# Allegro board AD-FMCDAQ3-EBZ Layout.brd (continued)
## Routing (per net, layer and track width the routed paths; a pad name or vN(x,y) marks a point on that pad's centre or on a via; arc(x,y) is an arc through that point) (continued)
FMC_SERDOUT0_N: length 40
  TOP w0.254: P501.A11 v4(68.13,22.21)
  BOTTOM w0.254: v4(68.13,22.21) 67.98,22.06 67.18,22.06 65.84,20.72 65.84,19.45 64.01,17.61 46.94,17.61 42.5,22.06 37.04,22.06 36.72,22.37 33.1,22.37 C20.1
FMC_SERDOUT0_P: length 40
  TOP w0.254: P501.A10 v4(68.13,21.4)
  BOTTOM w0.254: v4(68.13,21.4) 67.98,21.55 67.39,21.55 66.35,20.51 66.35,19.24 64.22,17.1 46.73,17.1 42.29,21.55 36.83,21.55 36.51,21.87 33.1,21.87 C8.1
FMC_SERDOUT1_N: length 35.5
  TOP w0.254: P501.C7 v4(65.59,17.1)
  BOTTOM w0.254: C85.1 33.1,20.98 35.96,20.98 36.53,20.41 41.74,20.41 46.31,15.83 63.88,15.83 64.87,16.82 65.31,16.82 v4(65.59,17.1)
FMC_SERDOUT1_P: length 35.4
  TOP w0.254: P501.C6 v4(65.59,16.32)
  BOTTOM w0.254: v4(65.59,16.32) 65.08,16.32 64.09,15.33 46.1,15.33 41.53,19.9 36.32,19.9 35.75,20.47 33.1,20.47 C84.1
FMC_SERDOUT2_N: length 40.9
  TOP w0.254: P501.A7 v4(68.13,17.13)
  BOTTOM w0.254: v4(68.13,17.13) 67.96,16.96 67.4,16.96 66.63,16.2 66.63,15.51 63.24,12.12 61.79,12.12 59.6,14.31 45.55,14.31 41.1,18.75 36.02,18.75 35.2,19.58 33.1,19.58 C87.1
FMC_SERDOUT2_P: length 40.9
  TOP w0.254: P501.A6 v4(68.13,16.32)
  BOTTOM w0.254: C86.1 33.1,19.07 34.99,19.07 35.81,18.25 40.89,18.25 45.34,13.8 59.39,13.8 61.57,11.62 63.45,11.62 67.14,15.3 67.14,15.99 67.61,16.46 67.99,16.46 68.08,16.37 v4(68.13,16.32)
FMC_SERDOUT3_N: length 39.4
  TOP w0.254: P501.A3 v4(68.28,12.02)
  BOTTOM w0.254: v4(68.28,12.02) 68.08,11.82 67.59,11.82 66.19,10.42 61.33,10.42 59.22,12.53 45.17,12.53 40.59,17.1 35.7,17.1 34.63,18.18 33.1,18.18 C92.1
FMC_SERDOUT3_P: length 39.4
  TOP w0.254: P501.A2 v4(68.28,11.31)
  BOTTOM w0.254: v4(68.28,11.31) 67.8,11.31 66.4,9.92 61.12,9.92 59.01,12.02 44.96,12.02 40.38,16.6 35.49,16.6 34.41,17.67 33.1,17.67 C88.1
FMC_SPI_SCLK: length 22.8
  TOP w0.152: v1(69.42,24.6) 69.42,29.04 69.55,29.17 69.55,34.5 71.07,36.03 72.73,36.03 72.98,36.28 R91.1
  L2_AGND w0.152: v1(64.3,23.7) 63.66,24.34 v2(63.66,24.65) ; v1(69.42,24.6) v2(69.42,23.96)
  L8_SIG w0.152: v2(69.42,23.96) 68.97,23.96 68.81,24.11 64.22,24.11 v2(63.66,24.65)
FMC_SPI_SDIO: length 23.4
  TOP w0.152: v1(69.93,26.12) 69.93,18.25 70.57,17.61 76.41,17.61 76.98,18.18 R115.1
  L2_AGND w0.152: v1(64.3,26.24) 64.3,26.21 v2(63.84,25.74) ; v1(69.93,26.12) v2(69.93,25.49)
  L8_SIG w0.152: v2(63.84,25.74) 64.34,25.74 64.6,25.49 v2(69.93,25.49)
FMC_SPI_SDIO_CTRL: length 12
  TOP w0.152: U9.5 v1(74.63,20.41)
  L2_AGND w0.152: v1(65.57,22.43) 65.62,22.43 v2(65.99,22.79) ; v1(74.63,20.41) v2(74.63,21.17)
  L8_SIG w0.152: v2(65.99,22.79) 66.65,23.45 68.46,23.45 70.36,21.55 74.25,21.55 v2(74.63,21.17)
FMC_SYSREF_N: length 39.2
  TOP w0.254: 30.56,41.87 v1(30.62,41.87) ; P501.D18 v1(64.03,30.97)
  L2_AGND w0.254: v1(30.62,41.87) v2(31.07,41.64) ; v1(64.03,30.97) v2(63.56,30.97)
  L8_SIG w0.254: v2(31.07,41.64) 32.4,41.64 33.18,40.85 41.74,40.85 42.37,41.49 45.17,41.49 48.98,37.68 55.9,37.68 62.91,30.67 63.25,30.67 v2(63.56,30.97)
FMC_SYSREF_N_A: length 3.7
  TOP w0.254: R112.2 29.86,41.8 R114.2 28.37,41.8 27.82,41.25 27.82,39.97 U7.71
FMC_SYSREF_P: length 39.2
  TOP w0.254: P501.D17 v1(64.05,30.16) ; R113.1 v1(31.51,40.98)
  L2_AGND w0.254: v1(64.05,30.16) v2(63.56,30.16) ; v1(31.51,40.98) v2(31.07,40.85)
  L8_SIG w0.254: v2(63.56,30.16) 62.7,30.16 55.69,37.17 48.77,37.17 44.96,40.98 42.58,40.98 41.95,40.34 32.97,40.34 32.19,41.13 31.35,41.13 v2(31.07,40.85)
FMC_SYSREF_P_A: length 3.7
  TOP w0.254: U7.70 28.33,41.04 28.58,41.3 28.97,41.3 R114.1 29.23,41.3 30.43,41.3 R113.2
FMC_VADJ: length 101.2
  TOP w0.254: U9.1 73.19,18.96 v1(72.73,18.5) ; C235.1 71.07,27.77 71.59,28.28 U13.1 ; R119.2 72.41,39.07 72.09,39.07 71.71,39.46 71.46,39.46 C236.1 71.07,42.12 71.59,42.63 U12.1
  TOP w0.305: P501.H40 P501.G39 v1(61.76,59.26) 61.76,60.12 64.72,63.08 R8.1 64.72,66.32 v4(64.03,67.01)
  L2_AGND w0.254: v1(72.73,18.5) v2(72.09,18.5) ; v1(71.07,39.71) v2(71.07,40.34) ; v1(71.07,25.36) v2(71.07,25.99) ; v1(43.9,56.85) v2(44.4,56.85)
  L2_AGND w0.305: v1(61.76,59.26) v2(62.41,58.61) v1(63.03,57.99)
  L3_SIG w0.305: v2(71.33,55.84) 71.96,55.2 71.96,52.16 70.44,50.63 70.44,45.04 71.07,44.41 v2(71.07,40.34) 70.69,39.96 70.69,31.2 71.07,30.82 v2(71.07,25.99) 71.07,19.52 v2(72.09,18.5)
  L8_SIG w0.305: v2(44.4,56.85) 43.64,57.62 43.64,60.54 44.4,61.3 51.77,61.3 54.46,58.61 v2(62.41,58.61) 63.79,57.24 69.93,57.24 v2(71.33,55.84)
LDO_VCO_2P5: length 4.2
  TOP w0.305: C103.1 23.07,31.58 C62.1 24.47,31.58 25.14,32.26 U7.15
LF_EXT_CAP: length 4.7
  TOP w0.152: U7.7 26.63,36.26 26.08,36.26 25.93,36.41 25.93,36.98 25.57,37.33 C2.1 R2.1
LF_PLL2: length 1.2
  TOP w0.152: R83.2 25.45,32.76 U7.14
OUT0_N: length 14.1
  BOTTOM w0.203: U1.52 27.47,49.09 27.45,49.11 26.43,49.11 26.27,49.26
  BOTTOM w0.254: 26.27,49.26 24.59,50.94 24.59,55.25 24,55.84 23.7,55.84 R22.1 22.43,55.84 21.93,55.84 20.91,54.82 T2.1
OUT0_P: length 14.1
  BOTTOM w0.203: U1.53 27.47,49.59 27.45,49.57 26.69,49.57 26.63,49.62
  BOTTOM w0.254: T2.3 20.91,57.36 21.93,56.35 22.43,56.35 R15.2 23.7,56.35 24.21,56.35 25.1,55.46 25.1,51.16 26.63,49.62
OUT1_N: length 14.9
  BOTTOM w0.203: U1.45 28.22,45.54 26.31,45.54 26.09,45.32
  BOTTOM w0.254: 26.09,45.32 24.27,43.51 24.27,38.33 24,38.06 23.7,38.06 R23.2 22.43,38.06 21.93,38.06 20.91,39.07 T1.3
OUT1_P: length 14.9
  BOTTOM w0.203: U1.44 26.57,45.09 26.44,44.96
  BOTTOM w0.254: 26.44,44.96 24.78,43.3 24.78,38.12 24.21,37.55 23.7,37.55 R25.1 22.43,37.55 21.93,37.55 20.91,36.53 T1.1
PWRGD: length 230
  TOP w0.152: v4(39.71,19.26) 38.94,18.5 37.8,18.5 37.51,18.21 U17.5 ; U19.5 17.39,59.44 v4(17.23,59.27)
  TOP w0.254: R32.2 v1(51.64,53.55) ; 9.35,51.65 v4(8.21,51.65)
  TOP w0.305: U4.1 51.18,50.63 50.84,50.63 50.54,50.94 50.54,53.34 R32.2 ; v4(9.73,5.17) 10.03,5.46 U5.5
  L2_AGND w0.152: v1(51.64,53.55) v2(52.15,53.55)
  L3_SIG w0.152: v4(69.05,31.96) 70.19,33.09 70.19,39 69.93,39.25 69.93,51.65 v4(71.33,53.04) ; v4(17.23,59.27) 17.23,59.01 15.96,57.74 12.27,57.74 11.38,56.85 11.38,54.82 v4(8.21,51.65) 7.32,50.76 7.32,43.77 8.26,42.83 8.26,42.82 11.38,39.7 11.38,11.13 9.23,8.98 9.23,5.67 v4(9.73,5.17) ; v4(51.39,7.45) 48.85,9.99 47.2,9.99 39.71,17.48 v4(39.71,19.26)
  L8_SIG w0.152: v4(8.21,51.65) 9.48,52.92 23.83,52.92 24.85,53.93 29.55,53.93 30.43,54.82 30.43,55.2 31.32,56.09 42.88,56.09 44.28,54.7 51.01,54.7 v2(52.15,53.55) 53.55,53.55 56.22,50.89 65.87,50.89 66.76,51.77 70.06,51.77 v4(71.33,53.04)
  L8_SIG w0.305: v4(51.39,7.45) 49.99,6.05 28.91,6.05 28.02,5.17 v4(9.73,5.17)
  BOTTOM w0.254: v4(69.05,31.96) 68.92,31.83 U3.21 ; v4(71.33,53.04) 71.2,52.92 U6.21
  BOTTOM w0.305: U11.7 v4(51.39,7.45)
SPI_SCLK: length 123.9
  TOP w0.152: R101.1 v1(28.66,28.09)
  L2_AGND w0.152: v2(28.66,28.72) v1(28.66,28.09) ; v2(73.23,48.09) v1(73.23,48.73)
  L3_SIG w0.152: v2(31.7,13.04) 31.32,13.04 30.82,13.55 30.82,13.8 30.05,14.56 30.05,23.2 32.21,25.36 32.21,26.63 31.83,27.01 30.37,27.01 v2(28.66,28.72) 28.66,29.17 28.91,29.42 28.91,30.82 27.89,31.84 27.89,34.76 25.93,36.72 25.93,40.15 v2(26.31,40.53) ; v2(73.23,48.09) 74.25,47.08 74.25,43.27 77.17,40.34 77.17,36.87 76.15,35.86 76.15,21.63 73.11,18.58 73.11,12.91 v2(72.09,11.9)
  L8_SIG w0.152: v2(31.7,13.04) 33.36,13.04 33.99,13.67 44.91,13.67 46.18,12.4 54.06,12.4 56.09,10.37 69.8,10.37 71.33,11.9 v2(72.09,11.9)
  L9_AGND w0.152: v2(31.7,13.04) 29.55,13.04 v3(28.4,11.9) ; v2(28.66,28.72) v3(28.59,28.66) ; v3(26.31,41.04) v2(26.31,40.53)
  BOTTOM w0.152: v3(26.31,41.04) 26.46,41.2 27.37,41.2 28.03,40.53 R106.2
SPI_SDIO: length 97.1
  TOP w0.152: R118.2 77.42,19.45 77.42,17.74 76.66,16.98 v1(76.66,11.64) ; R4.1 v1(29.55,28.09)
  L2_AGND w0.152: v1(76.66,11.64) v2(76.66,10.88) ; v2(29.8,28.67) 29.8,28.66 29.55,28.41 v1(29.55,28.09)
  L3_SIG w0.152: v2(31.7,11.9) 32.21,12.4 32.21,13.29 31.96,13.55 31.45,13.55 31.2,13.8 31.2,13.93 30.43,14.69 30.43,23.07 32.59,25.23 32.59,26.76 31.96,27.39 30.82,27.39 29.8,28.41 v2(29.8,28.67) 29.79,28.67 29.55,28.91 29.55,30.69 28.28,31.96 28.28,34.88 26.62,36.53 26.62,38.95 27.01,39.33 v2(27.01,40.22)
  L8_SIG w0.152: v2(76.66,10.88) 70.95,10.88 70.06,9.99 55.83,9.99 53.8,12.02 45.93,12.02 44.66,13.29 34.24,13.29 32.85,11.9 v2(31.7,11.9)
  L9_AGND w0.152: v3(30.43,28.66) 29.81,28.66 v2(29.8,28.67) ; v2(31.7,11.9) v3(31.2,11.9) ; v2(27.01,40.22) v3(27.01,40.79)
  BOTTOM w0.152: R107.2 29.08,40.36 28.86,40.14 27.65,40.14 v3(27.01,40.79) ; R105.1 30.43,12.66 v3(31.2,11.9)
SW1: length 17.3
  BOTTOM w0.305: 66.52,51.53 66.4,51.42 U6.7 ; 66.52,51.53 U6.6 ; 66.52,51.53 66.76,51.77 67.02,51.77 ; 63.6,60.42 63.43,60.59 R3.1 ; 66.63,56.22 67.02,55.83 U6.14 67.02,52.8 U6.PAD2 67.02,52.54 67.02,51.77 ; 67.02,51.77 U6.5
  BOTTOM w0.508: 63.58,58.12 L1.1 ; L1.1 64.38,56 64.34,55.97 ; L1.1 65.18,58.12 ; L1.1 64.38,60.32 ; CBST1.2 66.82,59.71
  vias: v3(64.15,59.71) v3(64.15,59.27) v3(64.15,57.62) v3(64.15,57.11) v3(64.15,56.6) v3(64.6,59.71) v3(64.6,59.27) v3(64.6,57.62) v3(64.6,57.11) v3(64.6,56.6) v3(66.64,53.26) v3(66.64,52.75) v3(66.64,52.22) v3(66.65,51.57) v3(67.15,53.74) v3(67.15,53.26) v3(67.15,52.75) v3(67.15,52.22) v3(67.14,51.55)
UNNAMED_2_AD9152_I234_I120: length 4
  TOP w0.152: v4(26.5,50.78) 25.66,51.62 R17.2
  BOTTOM w0.152: v4(26.5,50.78) 27.18,50.78 27.38,50.59 U1.55
UNNAMED_2_AD9152_I234_LDOBYP1: length 2.4
  TOP w0.356: v4(28.15,52.1) 28.15,52.18 29.01,53.04 C199.2
  BOTTOM w0.152: v4(28.15,52.1) 28.47,51.79 U1.1
UNNAMED_2_AD9152_I234_LDOBYP2: length 4.3
  BOTTOM w0.152: C39.1 40.21,47.71 38.88,47.71 38.76,47.59 U1.22
UNNAMED_2_AD9152_I234_PAPOUT0: length 3.5
  BOTTOM w0.152: U1.37 31.46,43.25 31.02,42.81 31.02,41.86 R20.1
UNNAMED_2_AD9152_I234_REFCLK: length 5.4
  BOTTOM w0.152: 27.77,55.71 28.66,54.82 29.55,54.82 29.96,54.41 U1.3
UNNAMED_2_AD9152_I234_REFCLK_1: length 4.3
  BOTTOM w0.152: U1.4 30.46,54.79 29.55,55.71
UNNAMED_2_AD9152_I234_RESETB: length 6
  BOTTOM w0.152: R122.1 33.99,55.08 32.96,54.05 U1.9
UNNAMED_2_AD9152_I234_SPICLK: length 3.9
  BOTTOM w0.152: U1.40 29.96,42.05 29.48,41.56 28.7,41.56 R106.1
UNNAMED_2_AD9152_I234_SPISDIO: length 3.5
  BOTTOM w0.152: U1.39 30.46,42.15 29.48,41.17 R107.1
UNNAMED_2_CAP_I167_N2: length 3.6
  TOP w0.508: C44.2 13.54,39.33 v4(12.53,38.31)
  BOTTOM w0.508: T4.5 13.8,38.31 v4(12.53,38.31)
UNNAMED_2_CAP_I184_N2: length 2.9
  TOP w0.508: C42.2 v4(12.53,56.09)
  BOTTOM w0.508: T3.5 v4(12.53,56.09)
UNNAMED_2_CNBNC5P_I224_CNTR: length 6.6
  BOTTOM w0.381: T4.3 9.22,40.34 TX_B.1
UNNAMED_2_CNBNC5P_I229_CNTR: length 6.6
  BOTTOM w0.381: TX_A.1 9.22,53.55 T3.1
UNNAMED_2_XFMRETC1_I243_N3: length 3.3
  BOTTOM w0.254: T2.4 15.96,57.36 14.69,58.63 T3.4
UNNAMED_2_XFMRETC1_I243_N4: length 3.3
  BOTTOM w0.254: T2.5 15.96,54.82 14.69,53.55 T3.6
UNNAMED_2_XFMRETC1_I246_N3: length 3.3
  BOTTOM w0.254: T1.4 15.96,39.07 14.69,40.34 T4.4
UNNAMED_2_XFMRETC1_I246_N4: length 3.3
  BOTTOM w0.254: T4.6 14.69,35.26 15.96,36.53 T1.5
UNNAMED_4_AD9528_I220_OUT3: length 0.7
  TOP w0.254: U7.58 34.33,40.62 C189.1
UNNAMED_4_AD9528_I220_OUT3N: length 0.7
  TOP w0.254: C185.1 33.83,40.57 U7.59
UNNAMED_4_AD9528_I220_OUT10: length 5.4
  TOP w0.203: C194.1 37.55,27.39 37.51,27.42 37.28,27.42 37.22,27.48 35.67,27.48 34.85,28.3 34.85,29.66 34.83,29.68 U7.34
UNNAMED_4_AD9528_I220_OUT10N: length 5.2
  TOP w0.203: C193.1 37.79,28.03 37.65,27.88 37.47,27.88 37.07,28.28 36.87,28.28 36.53,27.94 35.86,27.94 35.31,28.49 35.31,28.79 35.51,29 35.51,29.17 35.31,29.38 35.31,29.65 35.33,29.68 U7.35
UNNAMED_4_AD9528_I220_SCLK: length 1.5
  TOP w0.152: U7.22 28.83,29.21 28.4,28.79 R101.2
UNNAMED_4_AD9528_I220_SDIO: length 1.4
  TOP w0.152: U7.23 29.29,30.02 R4.2
UNNAMED_4_CAP_I87_N1: length 9.1
  TOP w0.254: R58.1 15.58,36.46 Y1.5 16.08,35.19 16.08,34.5 16.72,33.87 20.15,33.87 C75.1
UNNAMED_4_CAP_I87_N2: length 5.5
  TOP w0.254: U7.12 25.31,33.76 25.08,33.99 23.96,33.99 R5.2 23.2,33.99 22.31,33.99 C75.2
UNNAMED_4_CAP_I90_N1: length 9
  TOP w0.254: C74.1 20.02,35.52 19.64,35.52 19.26,35.14 19.26,34.63 19,34.38 17.03,34.38 16.71,34.69 16.71,35.05 Y1.4 17.35,36.46 R48.1
UNNAMED_4_CAP_I90_N2: length 5.5
  TOP w0.254: C74.2 22.31,34.5 23.2,34.5 23.58,34.88 23.96,34.5 25.29,34.5 25.52,34.27 26.62,34.27 U7.11
UNNAMED_4_CAP_I173_N1: length 2
  TOP w0.152: R2.2 C61.1
UNNAMED_4_CAP_I217_N2: length 0.9
  TOP w0.305: R83.1 24.66,32.79 C62.2
UNNAMED_4_RES_I223_N2: length 4.6
  TOP w0.508: R6.2 R1.1 11.94,31.71 Y1.1
UNNAMED_5_AD9680_I130_SCLK: length 4
  BOTTOM w0.152: R104.2 28.66,12.85 28.66,14.58 27.86,15.37 27.76,15.37 27.6,15.54 U100.36
UNNAMED_5_AD9680_I130_SDIO: length 4
  BOTTOM w0.152: R105.2 29.04,13.23 29.04,14.6 28.1,15.53 U100.35
UNNAMED_5_CAP_I52_N2: length 0.9
  BOTTOM w0.254: R103.1 19.42,29.99 19.03,29.6 C108.2
UNNAMED_5_CAP_I53_N2: length 0.9
  BOTTOM w0.254: C187.2 19.38,29.23 19.75,29.6 R102.1
UNNAMED_5_CAP_I54_N2: length 1.6
  BOTTOM w0.254: R111.1 20.2,30.42 ; 20.2,30.42 20.73,30.95 C107.2 ; 20.2,30.42 R110.2
UNNAMED_5_CAP_I67_N2: length 1.5
  BOTTOM w0.254: 20.26,10.67 20.78,10.15 C190.2 ; 20.26,10.67 R129.1 ; 20.26,10.67 R128.2
UNNAMED_5_CAP_I68_N2: length 0.8
  BOTTOM w0.254: C188.2 18.94,11.47 R54.1
UNNAMED_5_CAP_I69_N2: length 0.8
  BOTTOM w0.254: 19.46,12.01 19.46,11.99 R53.1
UNNAMED_5_CAP_I181_N2: length 9.1
  BOTTOM w0.254: R108.1 23.83,28.32 23.83,28.93 C105.2 23.92,31.05 22.69,32.28 20.64,32.28 R110.1 19.49,31.09 R103.2
UNNAMED_5_CAP_I182_N1: length 8.6
  BOTTOM w0.254: R102.2 20.93,29.69 R111.2 21.16,29.93 21.42,29.93 21.8,30.31 21.8,30.82 21.33,31.29 21.33,31.47 21.63,31.77 22.48,31.77 23.41,30.84 23.41,29.32 23.23,29.14 C197.1 23.32,28.93 23.32,28.32 R109.1
UNNAMED_5_CAP_I183_N2: length 8.8
  BOTTOM w0.254: R53.2 R128.1 21.81,11.38 22.05,11.13 22.05,10.63 21.67,10.25 21.67,9.74 21.85,9.56 22.63,9.56 23.63,10.55 23.63,12.25 ; C115.2 23.63,12.25 ; 23.63,12.25 23.63,13.05 R126.1
UNNAMED_5_CAP_I184_N1: length 9.3
  BOTTOM w0.254: C116.1 24.14,12.25 ; 24.14,12.25 24.14,13.15 R127.1 ; 24.14,12.25 24.14,10.34 22.84,9.05 21.64,9.05 21.08,9.61 20.53,9.61 20.43,9.71 19.8,9.71 R129.2 R54.2
UNNAMED_5_CNBNC5P_I49_CNTR: length 5.8
  BOTTOM w0.381: RX_A.1 R121.1 T101.5
UNNAMED_5_CNBNC5P_I70_CNTR: length 5.8
  BOTTOM w0.381: T103.4 R138.1 RX_B.1
UNNAMED_6_CN400PAKV2_I20_TDI: length 1.3
  TOP w0.152: P501.D31 P501.D30
UNNAMED_7_AD7291_I66_DCAP: length 1.9
  TOP w0.152: C216.2 49.73,57.44 U18.8
UNNAMED_7_AD7291_I66_VIN5: length 4.6
  TOP w0.152: U18.3 45.79,61.04 R66.1 R67.2
UNNAMED_7_AD7291_I66_VIN6: length 7.3
  TOP w0.152: U18.4 46.69,60.54 45.93,59.78 45.93,58.12 45.67,57.87 45.42,57.87 45.17,57.62 R24.1 R26.2
UNNAMED_7_AD7291_I66_VIN7: length 10.1
  TOP w0.152: U18.5 46.83,60.04 46.31,59.52 46.31,58 46.06,57.74 46.06,54.19 R27.1 R36.2
UNNAMED_7_AD7291_I66_VREF: length 3.1
  TOP w0.152: C219.2 47.51,57.04 48.6,58.12 48.98,58.12 49.23,58.38 U18.7
UNNAMED_7_ADN4661_I56_DIN: length 9.2
  TOP w0.381: v4(40.98,27.01) 41.48,26.5 R9.1 U15.2
  BOTTOM w0.381: v4(40.98,27.01) 40.09,27.89 J1.1
UNNAMED_7_DIOLED_I43_P: length 1.8
  BOTTOM w0.152: R34.2 CR1.A
UNNAMED_7_ICFXL4245_I164_A0: length 3.4
  TOP w0.152: R74.2 72.98,25.61 72.75,25.84 U13.3
UNNAMED_7_ICFXL4245_I164_A1: length 1.5
  TOP w0.152: R41.2 73.49,25.74 73.25,25.97 U13.4
UNNAMED_7_ICFXL4245_I164_A2: length 3.5
  TOP w0.152: R75.2 74,25.74 73.74,25.99 73.74,26.73 U13.5
UNNAMED_7_ICFXL4245_I164_A3: length 1.5
  TOP w0.152: U13.6 74.25,25.99 74.5,25.74 R45.2
UNNAMED_7_ICFXL4245_I164_A4: length 3.5
  TOP w0.152: R71.2 75.01,25.74 74.76,25.99 74.76,26.73 U13.7
UNNAMED_7_ICFXL4245_I164_A5: length 1.6
  TOP w0.152: R65.2 75.52,25.74 75.25,26.01 U13.8
UNNAMED_7_ICFXL4245_I164_A6: length 3.5
  TOP w0.152: R73.2 76.03,25.74 75.75,26.01 U13.9
UNNAMED_7_ICFXL4245_I164_A7: length 1.6
  TOP w0.152: R70.2 76.54,25.87 76.25,26.15 U13.10
UNNAMED_7_ICFXL4245_I164_B0: length 3.4
  TOP w0.152: U13.21 73.25,33.66 R82.1
UNNAMED_7_ICFXL4245_I164_B1: length 1.4
  TOP w0.152: R76.1 73.75,31.76 U13.20
UNNAMED_7_ICFXL4245_I164_B2: length 3.4
  TOP w0.152: R84.1 74.25,33.67 U13.19
UNNAMED_7_ICFXL4245_I164_B3: length 1.4
  TOP w0.152: U13.18 74.75,31.77 R77.1
UNNAMED_7_ICFXL4245_I164_B4: length 3.4
  TOP w0.152: R78.1 75.25,33.66 U13.17
UNNAMED_7_ICFXL4245_I164_B5: length 1.5
  TOP w0.152: U13.16 75.75,31.75 R116.2
UNNAMED_7_ICFXL4245_I164_B6: length 3.4
  TOP w0.152: U13.15 76.25,33.65 R81.2
UNNAMED_7_ICFXL4245_I164_B7: length 2.5
  TOP w0.152: U13.14 76.79,29.29 R117.2
UNNAMED_7_ICFXL4245_I164_OEN: length 1.5
  TOP w0.152: U13.22 72.75,31.74 R80.2
UNNAMED_7_ICFXL4245_I164_TRN: length 2.6
  TOP w0.152: R79.1 72.47,25.74 72.21,26 U13.2
UNNAMED_7_ICFXL4245_I213_A0: length 3.4
  TOP w0.152: U12.3 72.75,40.19 72.98,39.96 R91.2
UNNAMED_7_ICFXL4245_I213_A1: length 1.5
  TOP w0.152: R85.1 73.49,40.09 73.25,40.32 U12.4
UNNAMED_7_ICFXL4245_I213_A2: length 3.4
  TOP w0.152: R92.1 74,40.09 73.75,40.33 U12.5
UNNAMED_7_ICFXL4245_I213_A3: length 1.5
  TOP w0.152: R86.2 74.5,40.09 74.25,40.34 U12.6
UNNAMED_7_ICFXL4245_I213_A4: length 3.5
  TOP w0.152: U12.7 74.75,40.35 75.01,40.09 R89.2
UNNAMED_7_ICFXL4245_I213_A5: length 1.6
  TOP w0.152: R87.2 75.52,40.09 75.25,40.36 U12.8
UNNAMED_7_ICFXL4245_I213_A6: length 3.5
  TOP w0.152: R90.2 76.03,40.09 75.75,40.36 U12.9
UNNAMED_7_ICFXL4245_I213_A7: length 1.6
  TOP w0.152: R88.2 76.54,40.22 76.25,40.5 U12.10
UNNAMED_7_ICFXL4245_I213_B0: length 3.4
  TOP w0.152: R99.1 73.25,48.01 U12.21
UNNAMED_7_ICFXL4245_I213_B1: length 1.4
  TOP w0.152: U12.20 73.75,46.11 R100.2
UNNAMED_7_ICFXL4245_I213_B2: length 3.4
  TOP w0.152: U12.19 74.25,48.02 R93.2
UNNAMED_7_ICFXL4245_I213_B3: length 1.4
  TOP w0.152: U12.18 74.75,46.12 R94.1
UNNAMED_7_ICFXL4245_I213_B4: length 3.4
  TOP w0.152: U12.17 75.25,48.02 R97.1
UNNAMED_7_ICFXL4245_I213_B5: length 1.5
  TOP w0.152: R95.1 75.75,46.1 U12.16
UNNAMED_7_ICFXL4245_I213_B6: length 3.4
  TOP w0.152: U12.15 76.25,48 R98.1
UNNAMED_7_ICFXL4245_I213_B7: length 2.5
  TOP w0.152: R96.1 76.8,46.11 U12.14
UNNAMED_7_ICFXL4245_I213_OEN: length 1.5
  TOP w0.152: R120.2 72.75,46.09 U12.22
UNNAMED_7_ICFXL4245_I213_TRN: length 2.6
  TOP w0.152: R119.1 72.47,40.09 72.21,40.35 U12.2
UNNAMED_7_ICFXLH1T45_I232_A: length 1.4
  TOP w0.152: R115.2 76.01,18.96 U9.3
UNNAMED_7_ICFXLH1T45_I232_B: length 1.4
  TOP w0.152: U9.4 76.01,19.56 R118.1
UNNAMED_7_ICM24CXX_I21_E0: length 2.5
  TOP w0.152: U2.1 72.98,55.46 R10.2
UNNAMED_7_ICM24CXX_I21_E1: length 2.5
  TOP w0.152: U2.2 74.25,55.46 R11.2
UNNAMED_7_ICM24CXX_I21_WCN: length 5.1
  TOP w0.152: JP3.2 R29.2 74.25,64.73 U2.7
UNNAMED_7_NC7WZ17P6X_I12_Y1: length 4.5
  TOP w0.152: U4.6 47.56,50.62 v4(46.44,49.49)
  BOTTOM w0.152: R34.1 v4(46.44,49.49)
UNNAMED_7_RES_I67_N1: length 5.1
  TOP w0.152: U18.20 48.73,63.82 47.45,65.1 R12.1 R39.2
UNNAMED_7_RES_I85_N1: length 5.3
  TOP w0.152: U18.19 49.23,64.09 R59.1 R60.2
UNNAMED_7_RES_I87_N2: length 8.3
  TOP w0.152: R64.2 R63.1 53.55,64.86 50.63,64.86 49.73,63.96 U18.18
UNNAMED_7_RES_I91_N1: length 4.6
  TOP w0.152: U18.2 45.82,61.54 R62.2 R61.1
UNNAMED_7_RES_I93_N1: length 6.9
  TOP w0.152: U18.1 46.97,62.04 46.75,62.25 46.75,64.78 R42.2 R40.1
UNNAMED_8_ADM7154_I184_BYP: length 4.1
  TOP w0.305: C165.1 15.7,27.2 15.7,25.43 15.38,25.1 U8.3
UNNAMED_8_ADM7154_I184_REF: length 4.3
  TOP w0.305: U8.5 11.25,25.6 11,25.36 ; C183.1 10.11,26.56 10.11,25.81 10.56,25.36 11,25.36 ; 11,25.36 11.1,25.26 11.11,25.26 11.26,25.1 11.27,25.1 U8.6
UNNAMED_8_ADM7154_I184_VREG: length 2.2
  TOP w0.305: C178.1 14.87,22.02 U8.1
UNNAMED_8_ADP238X_I102_BST: length 3.4
  BOTTOM w0.254: CBST1.1 67.52,57.04 67.52,56.35 U6.15
UNNAMED_8_ADP238X_I102_COMP: length 7.7
  BOTTOM w0.254: U6.1 69.38,50.62 70.01,50 71.62,50 CC1.1 73.36,46.95 CC0.1
UNNAMED_8_ADP238X_I102_RT: length 3.4
  BOTTOM w0.254: U6.22 71.62,52.42 72.09,52.89 72.09,53.39 RT1.1
UNNAMED_8_ADP238X_I102_SS: length 2.7
  BOTTOM w0.254: CSS1.2 70.92,51.77 70.57,51.42 U6.24
UNNAMED_8_ADP238X_I102_VREG: length 2
  BOTTOM w0.254: CVREG1.2 68.02,49.13 U6.3
UNNAMED_8_ADP1755_I190_ADJ: length 5
  TOP w0.305: R38.1 R37.2 15.09,7.24 U5.9
UNNAMED_8_ADP1755_I190_SS: length 4.8
  TOP w0.305: C148.1 14.81,4.91 11.77,4.91 11.33,5.35 U5.7
UNNAMED_8_ADP1755_I190_VOUT1: length 15.8
  TOP w0.305: U5.13 U5.14 11.33,10.95 ; U5.13 12.47,10.11 ; U5.13 11.98,10.95 ; U5.11 U5.12 ; U5.11 13.74,8.54 ; U5.11 U5.10 13.74,7.89 ; U5.12 13.74,9.19 ; U5.12 12.9,9.68
  TOP w0.508: 12.53,11.2 C182.P ; C182.P 13.44,12.53 ; C182.P 11.61,12.53 ; E17.1 14.79,14.01 ; E17.1 13.93,12.79 ; E17.1 14.79,11.57 ; E17.1 15.66,12.79 ; 14.18,8.85 15.38,8.85 R37.1
UNNAMED_8_ADP7104_I66_SENSE: length 7.7
  BOTTOM w0.508: R44.2 R47.1 42.31,10.94 43.26,9.99 43.26,7.83 43.64,7.45 U11.2
UNNAMED_8_ADP7104_I66_VOUT: length 13
  TOP w0.508: 24.08,3.63 E20.1 ; E20.1 25.81,3.63 ; E20.1 24.94,2.42 ; E21.1 40.99,4.85 ; E21.1 40.99,2.42 ; E21.1 40.13,3.63 ; E21.1 41.86,3.63
  BOTTOM w0.508: 43.58,6.18 U11.1 44.66,5.55 ; C45.1 42.06,6.18 ; C45.1 41.19,5.27 ; C45.1 41.19,7.1 ; R47.2 41.99,7.58
  vias: v1(42.11,4.78) v1(42.11,4.02) v1(42.11,3.25) v1(42.12,2.5) v1(42.87,4.78) v1(42.87,4.02) v1(42.87,3.25) v1(42.88,2.5) v2(43.52,4.4) v2(43.52,3.64) v2(43.52,2.88) v2(44.28,4.4) v2(44.28,3.64) v2(44.28,2.88) v3(40.72,4.91) v3(40.72,4.15) v3(40.72,3.39) v3(41.48,4.91) v3(41.48,4.15) v3(41.48,3.39) v3(42.25,4.91) v3(42.25,4.15) v3(42.25,3.39)
UNNAMED_8_ADP7104_I68_SENSE: length 5.6
  TOP w0.508: 14.69,51.65 16.21,51.65 16.78,52.22 R46.1 R43.2
UNNAMED_8_ADP7104_I68_VOUT: length 14.1
  TOP w0.508: E12.1 17.71,45.5 ; E12.1 17.71,43.06 ; E12.1 16.85,44.28 ; 13.61,50.38 U10.1 ; U10.1 15.77,50.38 ; U10.1 14.69,49.74 ; C13.1 14.69,48.79 ; C13.1 15.6,47.93 ; C13.1 13.77,47.93 ; 16.85,47.58 E10.1 ; E10.1 17.71,48.8 ; E10.1 17.71,46.36 ; 16.84,50.31 R46.2 17.86,49.35
UNNAMED_8_CAP_I10_N2: length 2.3
  BOTTOM w0.254: CC1.2 75.54,49.96 RC1.2
UNNAMED_8_CAP_I92_N1: length 3.1
  TOP w0.305: 15.89,24.6 U8.2
  TOP w0.508: 17.69,29.55 E8.1 16.82,28.33
  vias: v1(17.1,29.55) v1(17.1,28.91) v1(17.12,28.15) v1(17.73,29.55) v1(17.84,28.91) v1(17.81,28.15) v1(32.34,26.25) v1(32.34,25.49) v1(32.34,24.85) v1(32.97,26.25) v1(32.97,25.49) v1(32.97,24.85) v2(19.13,27.96) v2(19.13,27.33) v2(19.7,28.47) v2(19.7,27.83) v2(31.07,26.37) v2(31.07,25.74) v2(31.7,26.37) v2(31.7,25.74)
UNNAMED_8_CAP_I104_N1: length 28.6
  BOTTOM w0: L11.1 65.13,49.3
  BOTTOM w0.152: 65.36,47.71 v3(65.49,47.58)
  BOTTOM w0.508: L1.2 62.02,60.37 ; L1.2 62.82,58.12 ; L1.2 62.02,56 62.06,55.97 ; L1.2 61.22,58.12 ; L11.1 63.71,47.71 ; CFB1.1 50.97,57.87 ; CFB1.1 50.25,58.63 ; CFB1.1 49.52,57.87
  BOTTOM w0.635: 52.1,58.76 CF3.2 ; CF3.2 53.42,57.64 ; CF3.2 53.42,59.88 ; CF3.2 54.74,58.76 ; CF2.2 57.54,58.76 ; CF2.2 56.22,59.88 ; CF2.2 54.89,58.76 ; CF2.2 56.22,57.64 ; 57.69,58.76 CF1.2 ; CF1.2 59.01,57.64 ; CF1.2 59.01,59.88 ; CF1.2 60.33,58.76
  BOTTOM w0.762: v3(64.72,49.87) 64.57,49.72 L11.1 65.36,47.71
  vias: v2(49.48,58) v2(50.25,58) v2(51.01,58) v2(51.77,60.28) v2(51.77,59.52) v2(51.77,58.76) v2(51.77,58) v2(63.2,48.98) v2(63.2,48.22) v2(63.2,46.69) v2(63.96,48.22) v2(63.96,47.46) v2(63.96,46.69) v2(64.72,48.22) v2(64.72,47.46) v2(64.72,46.69) v3(49.48,60.16) v3(49.48,59.52) v3(49.48,58.89) v3(50.25,60.16) v3(50.25,59.52) v3(50.25,58.89) v3(51.01,60.16) v3(51.01,59.52) v3(51.01,58.89) v3(63.96,50.63) v3(63.96,49.87) v3(64.72,50.63) v3(65.49,50.63) v3(65.49,49.87) v3(65.49,49.11) v3(65.49,48.35) v3(65.49,46.82)
UNNAMED_8_CAP_I104_N2: length 32.8
  L3_SIG w0.254: v2(50.25,56.09) 51.52,54.82 51.52,50.38 v2(54.95,46.95)
  L8_SIG w0.254: v2(72.22,46.44) 71.07,46.44 69.63,44.99 57.54,44.99 55.58,46.95 v2(54.95,46.95)
  L9_AGND w0.254: v3(72.22,45.81) v2(72.22,46.44) ; v3(50.25,56.6) v2(50.25,56.09) ; v3(54.95,47.46) v2(54.95,46.95)
  BOTTOM w0.254: RF1.2 71.67,45.81 v3(72.22,45.81)
UNNAMED_8_CAP_I171_N2: length 15.9
  BOTTOM w0.305: U6.18 69.49,54.72 ; U6.18 69.02,55.48 ; U6.18 U6.17 ; U6.17 68.52,55.48 ; U6.17 U6.16 68.02,55.48 ; 69.82,54.39 U6.19 70.58,53.92
  BOTTOM w0.508: CIN21.2 72.53,61.27 ; CIN21.2 73.5,60.16 ; CIN21.2 72.53,59.04 ; CIN11.2 72.53,58.86 ; CIN11.2 72.53,56.63 ; CIN11.2 73.5,57.74 ; LIN1.2 75.27,61.22 ; LIN1.2 75.27,59.34 ; LIN1.2 76.59,60.28 ; LIN1.2 73.94,60.28
UNNAMED_8_CAP_I177_N1: length 2.5
  BOTTOM w0.508: C237.1 67.21,64.63 R69.2
UNNAMED_8_RES_I185_N2: length 5.1
  BOTTOM w0.254: U6.2 68.52,49.99 68.66,49.84 69.07,49.84 70.06,48.85 RF2.2 70.06,47.89 71.06,47.04 RF1.1
UNNAMED_9_ADP238X_I75_BST: length 3.3
  BOTTOM w0.254: U3.15 65.24,35.71 CBST2.1
UNNAMED_9_ADP238X_I75_COMP: length 7.9
  BOTTOM w0.254: CC02.2 73.74,28.6 CC12.2 71.14,28.91 67.01,28.91 66.74,29.19 U3.1
UNNAMED_9_ADP238X_I75_RT: length 3.6
  BOTTOM w0.254: RT22.2 69.93,32.28 69.93,31.58 69.73,31.38 68.71,31.38 68.67,31.33 U3.22
UNNAMED_9_ADP238X_I75_SS: length 3.7
  BOTTOM w0.254: CSS2.2 70.82,30.18 68.92,30.18 68.77,30.33 U3.24
UNNAMED_9_ADP238X_I75_SW1: length 14.7
  BOTTOM w0.305: U3.7 64.12,30.33 64.24,30.45 ; 64.24,30.45 64.48,30.69 64.74,30.69 ; 64.24,30.45 U3.6 ; 64.6,34.88 64.74,34.74 U3.14 64.74,31.71 U3.PAD2 64.74,31.46 64.74,30.69 ; 64.74,30.69 U3.5
  BOTTOM w0.508: CBST2.2 66.06,38.57 64.72,38.57
  BOTTOM w1.016: 61.77,36.28 L10.1 ; L10.1 62.82,38.44 ; L10.1 61.77,40.6
  vias: v3(61.49,39.58) v3(61.49,39.1) v3(61.49,38.59) v3(61.49,37.98) v3(61.49,37.35) v3(61.99,39.58) v3(61.99,39.1) v3(61.99,38.59) v3(61.99,38.01) v3(61.99,37.35) v3(64.36,32.22) v3(64.36,31.71) v3(64.36,31.17) v3(64.36,30.46) v3(64.86,32.7) v3(64.86,32.22) v3(64.86,31.71) v3(64.86,31.17) v3(64.86,30.46)
UNNAMED_9_ADP238X_I75_VREG: length 2.7
  BOTTOM w0.254: U3.3 65.74,28.49 CVREG2.2
UNNAMED_9_ADP1741_I185_ADJ: length 6
  TOP w0.254: R50.2 R49.1 34.56,18.56 34.12,18.12 34.12,16.72 34.29,16.55 U17.9
UNNAMED_9_ADP1741_I185_SS: length 4.9
  TOP w0.254: U17.7 36.21,18.13 36.02,18.31 36.02,19.26 36.66,19.9 37.89,19.9 C169.2
UNNAMED_9_ADP1741_I185_VOUT: length 31.6
  TOP w0.254: R49.2 33.61,18.69 33.61,15.83
  TOP w0.305: U17.12 U17.11 ; U17.12 33.79,14.6 ; U17.12 34.63,14.11 ; U17.11 U17.10 33.68,15.9 33.48,15.71 ; U17.11 33.79,15.25 ; 36.21,12.84 U17.14 U17.13 ; 35.56,12.84 U17.13 ; U17.13 35.06,13.68
  TOP w0.508: E1.1 19.99,8.41 ; E1.1 19.99,5.97 ; E1.1 19.13,7.19 ; E1.1 20.86,7.19 ; E3.1 31.15,7.2 ; E3.1 29.42,7.2 ; E3.1 30.29,8.42 ; E3.1 30.29,5.98 ; E9.1 40.57,8.42 ; E9.1 41.44,7.2 ; E9.1 40.57,5.98 ; E9.1 39.71,7.2 ; 31.42,14.18 C170.P ; C170.P 32.34,12.85 ; C170.P 33.25,14.18 ; 20,10.68 E2.1 ; E2.1 20,13.12 ; E2.1 20.86,11.9 ; E2.1 19.13,11.9
UNNAMED_9_ADP1741_I188_ADJ: length 5.4
  TOP w0.254: R52.2 R51.1
  TOP w0.305: U19.9 20.27,58.06 R51.1
UNNAMED_9_ADP1741_I188_SS: length 2.3
  TOP w0.305: U19.7 18.69,59.45 v4(18.94,59.2)
  BOTTOM w0.508: v4(18.94,59.2) 20.12,59.2 C4.2
UNNAMED_9_ADP1741_I188_VOUT: length 28.4
  TOP w0.305: U19.13 19.84,63.96 ; U19.13 U19.14 18.69,64.8 ; U19.13 19.34,64.8 ; 21.36,61.74 21.42,61.68 21.42,58.95 22.12,58.25 R51.2 ; 21.11,61.74 U19.10 U19.11 ; U19.11 21.11,62.39 ; U19.11 U19.12 ; U19.12 20.27,63.53 ; U19.12 21.11,63.04
  TOP w0.508: E6.1 43.03,50.07 ; E6.1 43.03,47.63 ; E6.1 43.89,48.85 ; E6.1 42.17,48.85 ; E4.1 30.51,62.21 ; E4.1 28.07,62.21 ; E4.1 29.29,63.07 ; 40.87,58.68 E5.1 ; E5.1 41.73,59.9 ; E5.1 40.87,61.12 ; 24.39,62.21 E7.1 ; E7.1 25.61,63.07 ; E7.1 26.83,62.21 ; C222.P 23.48,63.46 ; C222.P 22.56,64.79 ; C222.P 21.65,63.46
UNNAMED_9_CAP_I146_N1: length 2.8
  BOTTOM w0.254: RC12.2 73.23,26.69 CC12.1
UNNAMED_9_CAP_I148_N1: length 29.8
  L8_SIG w0.254: v2(69.04,26.37) 68.66,25.99 64.98,25.99 64.6,26.37 62.82,26.37 62.44,25.99 59.39,25.99 57.49,27.9 54.56,27.9 v2(53.55,26.88) 53.04,27.39 53.04,28.79 53.55,29.3 53.55,33.61 v2(50.75,36.41)
  L9_AGND w0.254: v3(53.55,26.37) v2(53.55,26.88) ; v3(50.25,36.41) v2(50.75,36.41) ; v3(69.04,25.87) v2(69.04,26.37)
UNNAMED_9_CAP_I148_N2: length 25.1
  BOTTOM w0.508: 55.83,38.21 CF4.2 ; CF4.2 55.83,40.45 ; CF4.2 54.51,39.33 ; CF4.2 57.16,39.33 ; CFB2.2 50.25,39.34 ; CFB2.2 49.13,38.38 ; CFB2.2 51.36,38.38 ; 51.72,39.33 CF5.2 ; CF5.2 54.36,39.33 ; CF5.2 53.04,38.21 ; CF5.2 53.04,40.45
  BOTTOM w0.762: 59.9,24.77 L12.1 ; L12.1 57.38,25.43 ; L12.1 62.41,25.43 ; L12.1 59.9,26.5
  BOTTOM w1.016: L10.2 59.3,40.6 ; L10.2 59.3,36.28 ; L10.2 58.25,38.44
  vias: v2(50.25,39.2) v2(50.25,38.57) v2(51.01,39.2) v2(51.01,38.57) v2(51.77,40.47) v2(51.77,39.84) v2(51.77,39.2) v2(51.77,38.57) v2(54.82,27.26) v2(54.82,26.5) v2(55.58,27.26) v2(55.58,26.5) v2(56.34,27.26) v2(57.1,27.26) v3(49.48,40.73) v3(49.48,40.22) v3(49.48,39.71) v3(50.25,40.73) v3(50.25,40.22) v3(50.25,39.71) v3(51.01,40.73) v3(51.01,40.22) v3(51.01,39.71) v3(56.34,26.63) v3(56.34,25.87) v3(56.34,25.1) v3(56.34,24.34) v3(57.1,26.63) v3(57.1,25.87) v3(57.1,25.1) v3(57.1,24.34) v3(57.87,24.34) v3(58.63,24.34)
UNNAMED_9_CAP_I180_N2: length 15.9
  BOTTOM w0.305: 65.74,34.39 U3.16 U3.17 ; 68.3,32.83 U3.19 67.54,33.3 ; U3.18 66.74,34.39 ; U3.18 U3.17 ; U3.18 67.21,33.63 ; U3.17 66.24,34.39
  BOTTOM w0.508: CIN12.2 73.04,40.19 ; CIN12.2 73.04,37.96 ; CIN12.2 74.01,39.07 ; 74.83,38.82 LIN2.2 ; LIN2.2 76.15,39.76 ; LIN2.2 76.15,37.88 ; LIN2.2 77.48,38.82 ; CIN22.2 74.01,36.66 ; CIN22.2 73.04,35.54 ; CIN22.2 73.04,37.78
UNNAMED_9_RES_I163_N1: length 38.8
  L3_SIG w0.203: v4(66.69,63.09) 66.15,62.54 66.15,59.67 66.78,59.04 66.78,44.43 66.43,44.08 66.43,35.95 68.23,34.15 68.23,32.53 68.23,32.53 68.23,31.18 68.57,30.83 v4(68.99,30.83)
  BOTTOM w0.305: U3.23 v4(68.99,30.83) ; v4(66.69,63.09) R57.1 R3.2
UNNAMED_9_RES_I176_N1: length 4.6
  BOTTOM w0.254: R21.1 R7.2 66.24,27.97 U3.2
VIO_B_M2C: length 11.3
  TOP w0.305: R8.2 63.45,63.08 60.41,60.03 57.46,60.03 P501.K40 P501.J39

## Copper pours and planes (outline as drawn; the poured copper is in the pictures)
GND on TOP (solid shape): 14.46,22.78 12.65,22.78 12.65,23.4 14.46,23.4
GND on BOTTOM (solid shape): 49.19,35.57 51.3,35.57 51.3,37.55 51.78,37.55 51.78,35.48 54.3,35.48 54.3,37.55 54.58,37.55 54.58,35.48 57.09,35.48 57.09,37.55 57.48,37.55 57.48,35.39 63.48,35.39 64.33,34.54 64.33,34.43 64.24,34.33 64.21,34.33 63.94,34.2 63.83,33.92 63.83,33.34 63.83,33.31 63.76,33.24 63.73,33.24 63.14,33.24 62.78,33.01 62.82,32.58 62.74,32.33 62.82,32.08 62.74,31.83 62.82,31.58 62.74,31.33 62.82,31.08 62.74,30.83 62.82,30.58 62.77,30.49 62.74,30.4 62.74,30.36 62.56,30.3 60,32.85 59.89,32.85 59.89,35.05 57.37,35.05 57.37,32.85 57.09,32.85 57.09,35.05 54.58,35.05 54.58,32.85 54.3,32.85 54.3,35.05 51.78,35.05 51.78,32.85 51.5,32.85 51.5,35.05 48.99,35.05 48.99,32.85 47.83,32.85 47.83,37.55 49.19,37.55
GND on L5_PWR (solid shape): 28.78,17.1 21.93,17.1 21.93,23.96 28.78,23.96
GND on L5_PWR (solid shape): 34.5,32.09 28.66,32.09 28.66,37.93 34.5,37.93
GND on L5_PWR (solid shape): 35.39,44.66 29.04,44.66 29.04,51.01 35.39,51.01
GND on L6_PWR (solid shape): 28.78,17.1 21.93,17.1 21.93,23.96 28.78,23.96
GND on L6_PWR (solid shape): 34.5,32.09 28.53,32.09 28.53,38.06 34.5,38.06
GND on L6_PWR (solid shape): 35.39,44.66 29.04,44.66 29.04,51.01 35.39,51.01
GND on BOTTOM: 22.92,1.02 22.92,4.32 1.02,4.32 1.02,63.07 7.32,63.07 7.32,65.38 18.12,65.38 18.12,67.98 69.73,67.98 70.06,67.65 70.06,66.76 70.72,66.1 71.68,66.1 72.34,66.76 72.34,67.65 72.68,67.98 77.78,67.98 77.78,1.02 ; 15 cut-outs
GND on BOTTOM: 28.66,37.93 28.66,32.09 34.5,32.09 34.5,37.93
GND on L2_AGND: 22.92,1.02 22.92,4.32 1.02,4.32 1.02,63.07 7.32,63.07 7.32,65.38 18.12,65.38 18.12,67.98 77.78,67.98 77.78,1.02 ; 32 cut-outs
GND on L3_SIG: 22.92,1.02 22.92,4.32 1.02,4.32 1.02,63.07 7.32,63.07 7.32,65.38 18.12,65.38 18.12,67.98 77.78,67.98 77.78,1.02 ; 38 cut-outs
GND on L4_AGND: 22.92,1.02 22.92,4.32 1.02,4.32 1.02,63.07 7.32,63.07 7.32,65.38 18.12,65.38 18.12,67.98 77.78,67.98 77.78,1.02
GND on L6_PWR: 50.82,1.02 50.82,35.58 43.2,35.58 43.2,56.92 77.78,56.92 77.78,1.02 ; 1 cut-out
GND on L7_AGND: 22.92,1.02 22.92,4.32 1.02,4.32 1.02,63.07 7.32,63.07 7.32,65.38 18.12,65.38 18.12,67.98 77.78,67.98 77.78,1.02 ; 1 cut-out
GND on L8_SIG: 22.92,1.02 22.92,4.32 1.02,4.32 1.02,63.07 7.32,63.07 7.32,65.38 18.12,65.38 18.12,67.98 77.78,67.98 77.78,1.02 ; 41 cut-outs
GND on L9_AGND: 22.92,1.02 22.92,4.32 1.02,4.32 1.02,63.07 7.32,63.07 7.32,65.38 18.12,65.38 18.12,67.98 77.78,67.98 77.78,1.02 ; 19 cut-outs
P1V7 on TOP: 18.24,63.46 18.24,65.36 12.78,65.36 12.78,62.44 15.07,62.44 15.07,60.28 16.85,60.28 16.85,63.46
P1V7 on TOP: 36.66,14.18 36.66,12.47 36.75,12.24 36.97,12.15 38.31,12.15 38.31,10.88 41.67,10.88 41.99,11.01 42.12,11.32 42.12,14.44 39.83,14.44 39.83,17.17 39.74,17.39 39.51,17.48 37.93,17.48 37.93,14.18
P1V7 on BOTTOM: 59.9,32.6 47.58,32.6 47.58,25.99 48.6,24.98 55.58,24.98 55.58,27.26 62.82,27.26 62.82,29.68
P1V7 on L2_AGND: 37.42,12.66 37.42,9.99 42.12,9.99 42.12,12.66
P1V7 on L2_AGND: 14.81,64.47 14.81,62.44 12.02,62.44 12.02,64.47
P1V7 on L3_SIG: 11.64,61.05 11.64,64.47 12.27,65.11 17.99,65.11 19.77,66.89 45.93,66.89 45.93,54.31 45.42,53.81 45.42,51.65 46.44,50.63 46.44,38.06 49.61,34.88 49.61,32.72 46.06,32.72 43.26,35.52 43.26,50.25 41.61,51.9 41.61,63.33 24.72,63.33 22.43,61.05 19.64,61.05 19.51,61.17 19.51,62.95 19.26,63.2 17.48,63.2 17.23,62.95 17.23,61.3 16.97,61.05
P1V7 on L6_PWR: 37.36,1.02 37.36,26.82 43.2,26.82 43.2,34.95 50.18,34.95 50.18,1.02 ; 2 cut-outs
P1V7 on L9_AGND: 48.98,29.55 48.98,32.85 49.48,32.85 49.48,34.63 47.71,34.63 47.71,32.47 47.83,32.34 47.83,29.55
P3V3_CLK_OUT on L2_AGND: 36.15,24.85 36.15,28.03 38.18,28.03 38.18,24.85
P3V3_CLK_OUT on L5_PWR: 33.29,27.45 33.29,28.98 28.08,28.98 28.08,41.8 42.82,41.8 42.82,27.45
P3V3_CLK_PLL on TOP: 19.51,28.53 19.51,30.31 23,30.31 23,28.53
P3V3_CLK_PLL on L2_AGND: 20.53,30.12 22.94,30.12 22.94,28.47 20.53,28.47
P3V3_CLK_PLL on L6_PWR: 20.34,27.45 20.34,39.39 22.82,39.39 24.6,41.17 42.56,41.17 42.56,27.45 ; 1 cut-out
P3V6 on TOP: 5.8,22.95 5.8,25.87 9.48,25.87 10.5,24.85 12.4,24.85 12.4,23.89 12.25,23.73 12.25,23.1 12.1,22.95
P3V6 on TOP: 45.8,42.5 45.8,37.93 51.9,37.93 51.9,42.5
P3V6 on TOP: 13.16,47.58 7.32,47.58 7.32,50.25 6.43,50.89 6.43,53.68 7.32,54.57 8.21,54.57 8.21,52.92 7.57,52.28 7.57,51.39 8.21,50.76 10.37,50.76 11,50.12 13.16,50.12
P3V6 on TOP: 6.69,41.11 6.69,43.39 8.34,43.39 8.34,44.92 11.77,44.92 11.77,43.39 9.73,43.39 9.73,41.11
P3V6 on BOTTOM: 49.36,4.91 54.18,4.91 54.18,11.13 49.36,11.13
P3V6 on BOTTOM: 52.07,46.44 49.22,46.44 47.83,47.83 47.83,52.03 63.07,52.03 63.45,51.65 63.45,51.14 63.45,49.61 62.95,49.11 62.95,46.44 62.44,46.44 62.44,49.23 61.17,49.23 61.17,46.44 55.78,46.44 55.78,48.41 52.07,48.41
P3V6 on L2_AGND: 12.78,47.58 12.78,49.36 8.46,49.36 8.46,47.58
P3V6 on L2_AGND: 47.71,39.33 47.71,41.36 51.01,41.36 51.01,39.33
P3V6 on L2_AGND: 5.92,23.2 5.92,25.87 7.96,25.87 7.96,23.2
P3V6 on L5_PWR: 47.26,1.02 47.26,11.32 72.79,11.32 72.79,32.41 58.18,32.41 58.18,41.42 49.29,41.42 49.29,39.14 43.45,39.14 43.45,59.33 13.35,59.33 13.35,4.32 1.02,4.32 1.02,63.07 7.32,63.07 7.32,65.38 18.12,65.38 18.12,67.98 48.53,67.98 48.53,55.14 56.53,55.14 56.53,45.74 65.3,45.74 65.3,42.95 77.78,42.95 77.78,1.02 ; 6 cut-outs
P3V6 on L9_AGND: 51.01,11.13 51.01,8.34 53.8,8.34 53.8,11.13
P3V6 on L9_AGND: 48.09,53.55 48.09,50 50.88,50 50.88,53.55
(no net) on TOP: 22.92,1.02 22.92,4.32 22.76,4.32 22.76,4.84 26.62,4.84 26.62,4.07 27.18,4.07 27.23,4.12 27.23,4.78 28.55,4.78 28.71,4.63 28.96,4.63 29.04,4.71 28.77,4.99 22.61,4.99 22.61,4.32 8.57,4.32 8.18,4.71 8.18,6.08 8.97,6.87 8.95,6.89 8.13,6.89 7.42,7.6 7.42,9.86 6.18,9.86 5.47,9.15 5.47,8.59 5.26,8.39 1.02,8.39 1.02,63.07 10.62,63.07 10.62,65.38 18.12,65.38 18.12,67.98 43.2,67.98 43.2,63.84 45.29,61.74 46.82,61.74 46.88,61.81 46.88,67.98 50.44,67.98 50.44,63.01 50.94,62.51 51.14,62.51 51.14,64.16 51.45,64.47 53.68,64.47 54.12,64.92 56.79,64.92 57.04,65.17 57.04,67.98 77.78,67.98 77.78,1.02 ; 40 cut-outs
3P3_SUP on TOP: 48.47,37.3 48.47,32.22 51.9,32.22 51.9,37.3
3P3_SUP on L2_AGND: 49.74,34.38 49.74,32.6 49.23,32.6 49.23,31.07 51.9,31.07 51.9,34.38
3P3_SUP on L5_PWR: 43.45,11.96 43.45,32.91 50.82,32.91 50.82,25.42 58.18,25.42 58.18,31.77 72.15,31.77 72.15,11.96
3P3_XO on TOP: 8.08,34.5 8.08,35.77 9.73,35.77 9.99,36.03 9.99,37.17 10.24,37.55 10.24,38.19 9.99,38.44 8.97,38.44 8.97,40.34 9.99,40.34 10.37,40.73 12.15,40.73 12.15,37.8 13.04,36.92 13.04,35.39 12.15,34.5
ADC_1P2_AVDD on L2_AGND: 25.86,7.83 25.86,6.05 23.96,6.05 23.96,7.83
ADC_1P2_AVDD on L5_PWR: 22.92,1.02 22.92,4.32 13.99,4.32 13.99,28.34 21.29,28.34 21.29,25.68 20.59,24.98 20.59,14.63 21.67,14.63 21.67,8.15 24.66,8.15 24.66,1.02
ADC_1P2_AVDD_SR on L2_AGND: 26.12,12.28 26.12,10.12 24.47,10.12 24.47,12.28
ADC_1P2_DRVDD on L2_AGND: 45.17,6.05 45.17,7.96 46.44,7.96 46.44,6.05
ADC_1P2_DRVDD on L5_PWR: 38.75,1.02 38.75,16.53 33.29,16.53 33.29,26.82 42.82,26.82 42.82,11.32 46.63,11.32 46.63,1.02
ADC_1P2_DVDD on L2_AGND: 34.88,6.05 34.88,7.96 36.15,7.96 36.15,6.05
ADC_1P2_DVDD on L6_PWR: 28.08,1.02 28.08,23.58 28.72,24.21 28.72,26.82 36.72,26.82 36.72,1.02
ADC_2P5_AVDD on L2_AGND: 17.1,16.34 17.1,13.55 19,13.55 19,16.34
ADC_2P5_AVDD on L6_PWR: 22.92,1.02 22.92,4.32 17.04,4.32 17.04,26.82 18.75,26.82 18.87,26.69 20.34,26.69 20.34,26.82 28.08,26.82 28.08,24.47 27.45,23.84 27.45,1.02
ADC_3P3_AVDD on L2_AGND: 29.29,2.75 29.29,4.66 30.69,4.66 30.69,2.75
ADC_3P3_AVDD on L5_PWR: 25.29,1.02 25.29,8.78 22.31,8.78 22.31,15.26 21.23,15.26 21.23,24.72 21.93,25.42 21.93,28.34 27.45,28.34 27.64,28.15 27.64,24.98 29.55,24.98 30.18,24.22 30.18,16.09 29.61,15.52 25.42,15.52 25.42,11.77 29.03,11.77 31.39,9.42 31.39,1.02
ADC_3P3_SPIVDD on L2_AGND: 36.66,2.75 36.66,5.17 35.26,5.17 35.26,2.75
ADC_3P3_SPIVDD on L5_PWR: 32.02,1.02 32.02,9.68 29.3,12.4 26.05,12.4 26.05,14.88 30.24,14.88 30.82,15.45 30.82,24.85 30.24,25.49 28.08,25.49 28.08,28.34 32.66,28.34 32.66,15.9 38.12,15.9 38.12,1.02
DAC_1P2_CVDD12 on L2_AGND: 24.72,57.87 24.72,55.2 27.01,55.2 27.01,57.87
DAC_1P2_CVDD12 on L6_PWR: 20.34,45.49 20.34,60.98 28.72,60.98 28.72,54 29.86,54 29.86,45.49
DAC_1P2_DVDD12 on L2_AGND: 39.2,55.84 39.2,58.89 37.04,58.89 37.04,55.84
DAC_1P2_DVDD12 on L5_PWR: 28.08,42.44 28.08,58.7 42.82,58.7 42.82,56.16 34.05,56.16 34.05,42.44
DAC_1P2_PVDD12 on L2_AGND: 32.57,59.04 32.57,60.66 30.82,60.66 30.82,59.04
DAC_1P2_PVDD12 on L6_PWR: 30.5,45.49 30.5,54.63 29.35,54.63 29.35,60.98 35.45,60.98 35.45,54.5 38.63,54.5 38.63,45.49
DAC_1P2_SVDD12 on TOP: 34.75,43.39 34.75,42 37.55,42 37.55,43.39
DAC_1P2_SVDD12 on BOTTOM: 34.5,43.27 34.5,42.38 36.91,42.38 36.91,43.27
DAC_1P2_SVDD12 on L2_AGND: 40.85,44.79 40.85,47.71 38.97,47.71 38.97,46.82 39.32,46.82 39.32,44.79
DAC_1P2_SVDD12 on L5_PWR: 34.69,42.44 34.69,55.52 42.82,55.52 42.82,42.44
DAC_3P3_AVDD33 on TOP: 21.54,51.84 21.36,51.76 21.29,51.58 21.29,49.23 19.89,49.23 19.89,46.19 21.42,46.19 23.39,48.15 23.39,51.58 23.31,51.76 23.13,51.84
DAC_3P3_AVDD33 on L5_PWR: 13.99,28.98 13.99,58.7 27.45,58.7 27.45,28.98
DAC_3P3_IOVDD33 on TOP: 19.89,45.42 19.89,43.14 20.78,42.25 20.78,40.6 22.69,40.6 22.69,42.63 21.67,43.65 21.67,45.17 21.42,45.42
DAC_3P3_IOVDD33 on L2_AGND: 20.78,42.38 20.78,40.47 23.45,40.47 23.45,42.38
DAC_3P3_IOVDD33 on L6_PWR: 20.34,40.03 20.34,44.85 39.26,44.85 39.26,55.14 36.09,55.14 36.09,60.98 42.56,60.98 42.56,41.8 24.33,41.8 22.56,40.03
FMC_3P3V on TOP: 9.61,7.71 7.83,7.71 7.83,13.55 10.88,13.55 10.88,9.61 9.61,9.61
FMC_3P3V on L2_AGND: 63.45,53.8 63.45,59.64 65.1,59.64 65.1,58.88 66.12,58.88 66.12,57.36 64.72,57.36 64.72,53.8
FMC_3P3V on L2_AGND: 10.11,13.55 10.11,11.52 7.45,11.52 7.45,13.55
FMC_3P3V on L6_PWR: 1.02,4.32 1.02,63.07 7.32,63.07 7.32,65.38 18.12,65.38 18.12,67.98 77.78,67.98 77.78,57.55 43.2,57.55 43.2,61.62 19.7,61.62 19.7,27.45 16.4,27.45 16.4,4.32 ; 5 cut-outs
FMC_12P0V on BOTTOM: 74.5,40.73 74.5,43.65 77.78,43.65 77.78,40.73
FMC_12P0V on BOTTOM: 76.92,62.19 76.92,67.01 73.61,67.01 73.61,65.24 71.58,65.24 71.58,61.93 73.74,61.93 74,62.19
FMC_12P0V on L2_AGND: 64.97,56.35 64.97,52.66 66.37,52.66 66.37,56.35
FMC_12P0V on L5_PWR: 65.93,43.58 65.93,49.93 64.91,49.93 64.91,67.98 77.78,67.98 77.78,43.58
FMC_12P0V on L9_AGND: 73.74,65.11 73.74,62.44 76.79,62.44 76.79,65.11
FMC_12P0V on L9_AGND: 77.68,42.38 77.68,45.04 74.63,45.04 74.63,42.38
SW1 on BOTTOM: 67.01,55.58 66.63,55.97 65.49,55.97 65.23,55.71 63.33,55.71 63.33,60.54 67.14,60.54 67.14,55.71
SW1 on L9_AGND: 66.27,51.18 66.27,54.95 65.51,55.71 64.32,55.71 63.33,56.7 63.33,60.54 67.14,60.54 67.49,60.18 67.49,51.43 67.24,51.18
UNNAMED_8_ADP1755_I190_VOUT1 on TOP: 11,13.55 11,9.61 12.4,9.61 12.4,7.71 14.43,7.71 14.43,10.88 16.34,10.88 16.34,14.44 13.42,14.44 13.42,13.8 13.16,13.55
UNNAMED_8_ADP7104_I66_VOUT on TOP: 22.92,1.03 22.92,4.68 26.49,4.68 26.49,2.24 39.44,2.24 39.44,5.29 43.26,5.29 43.26,1.03
UNNAMED_8_ADP7104_I66_VOUT on BOTTOM: 45.42,3.13 45.42,6.82 42.75,6.82 42.75,7.83 40.47,7.83 40.47,3.13
UNNAMED_8_ADP7104_I66_VOUT on L2_AGND: 41.86,5.04 41.86,2.24 44.53,2.24 44.53,5.04
UNNAMED_8_ADP7104_I66_VOUT on L9_AGND: 40.47,5.17 40.47,2.63 44.53,2.63 44.53,5.17
UNNAMED_8_ADP7104_I68_VOUT on TOP: 13.67,50.63 13.42,50.38 13.42,47.46 15.58,47.46 15.58,43.39 16.34,42.63 18.62,42.63 18.62,49.23 17.86,49.23 17.86,50.63
UNNAMED_8_CAP_I92_N1 on TOP: 15.45,24.6 16.02,25.17 16.02,29.55 16.02,29.56 16.02,30.68 18.05,30.68 18.05,27.07 17.73,26.76 17.73,24.34 15.45,24.34
UNNAMED_8_CAP_I92_N1 on L2_AGND: 16.85,29.8 16.85,27.01 19.26,27.01 20.02,27.77 20.02,29.8
UNNAMED_8_CAP_I92_N1 on L2_AGND: 33.23,26.63 33.23,24.6 30.82,24.6 30.82,26.63
UNNAMED_8_CAP_I92_N1 on L7_AGND: 18.37,25.23 18.37,28.05 18.85,28.53 32.24,28.53 32.24,25.23
UNNAMED_8_CAP_I104_N1 on BOTTOM: 62.95,60.54 62.95,55.71 60.91,55.71 60.91,57.36 47.83,57.36 47.83,60.54
UNNAMED_8_CAP_I104_N1 on BOTTOM: 63.45,46.44 63.45,49.23 63.71,49.49 63.71,50.89 65.74,50.89 65.74,46.44 65.23,46.44 65.23,49.23 63.96,49.23 63.96,46.44
UNNAMED_8_CAP_I104_N1 on L5_PWR: 57.17,46.38 57.17,55.77 49.17,55.77 49.17,67.98 64.28,67.98 64.28,49.3 65.3,49.3 65.3,46.38
UNNAMED_8_CAP_I104_N1 on L9_AGND: 65.74,50.89 65.74,46.44 62.95,46.44 62.95,50.89
UNNAMED_8_CAP_I104_N1 on L9_AGND: 49.1,60.54 49.1,57.74 52.02,57.74 52.02,60.54
UNNAMED_8_CAP_I171_N2 on BOTTOM: 68.28,56.73 67.9,56.35 67.9,54.31 69.42,54.31 69.42,53.81 70.69,53.81 71.46,54.57 76.92,54.57 76.92,61.68 71.84,61.68 71.84,56.73
UNNAMED_9_ADP238X_I75_SW1 on BOTTOM: 64.72,34.5 63.58,35.65 60.79,35.65 60.79,41.36 64.98,41.36 64.98,34.76
UNNAMED_9_ADP238X_I75_SW1 on L9_AGND: 64.11,30.11 64.11,35.11 63.58,35.65 62.26,35.65 60.79,37.12 60.79,41.23 64.98,41.23 65.33,40.88 65.33,30.36 65.08,30.11
UNNAMED_9_ADP1741_I185_VOUT on TOP: 18.88,5.55 18.88,13.67 21.35,13.67 21.35,10.37 29.8,10.37 30.05,10.47 30.18,10.7 30.18,14.56 30.29,14.83 30.56,14.94 33.23,14.94 33.23,16.09 35.13,16.09 35.13,14.18 36.4,14.18 36.4,12.15 34.12,12.15 33.85,12.04 33.74,11.77 33.74,10.75 33.85,10.48 34.12,10.37 41.61,10.37 41.88,10.26 41.99,9.99 41.99,5.55 39.45,5.55 39.45,8.59 31.96,8.59 31.69,8.48 31.58,8.21 31.58,5.86 31.48,5.64 31.26,5.55 29.48,5.55 29.26,5.64 29.16,5.86 29.16,8.21 29.05,8.48 28.78,8.59 21.29,8.59 21.29,5.55
UNNAMED_9_ADP1741_I188_VOUT on TOP: 21.54,62.44 23.7,62.44 23.7,61.55 40.21,61.55 40.21,58.25 41.23,58.25 41.23,47.2 44.15,47.2 44.15,50.63 43.13,50.63 43.13,63.46 32.59,63.46 32.59,65.36 18.5,65.36 18.5,63.46 19.77,63.46 19.77,61.43 21.54,61.43
UNNAMED_9_CAP_I148_N2 on BOTTOM: 55.96,27.01 55.96,24.09 62.95,24.09 62.95,27.01
UNNAMED_9_CAP_I148_N2 on BOTTOM: 60.28,35.65 57.74,35.65 57.74,37.8 47.58,37.8 47.58,41.36 60.28,41.36
UNNAMED_9_CAP_I148_N2 on L5_PWR: 51.45,26.06 51.45,33.55 43.45,33.55 43.45,38.5 49.93,38.5 49.93,40.79 57.55,40.79 57.55,26.06
UNNAMED_9_CAP_I148_N2 on L9_AGND: 49.23,40.98 49.23,38.31 52.02,38.31 52.02,40.98
UNNAMED_9_CAP_I148_N2 on L9_AGND: 58.88,24.09 58.88,26.37 57.74,27.52 54.56,27.52 54.56,24.09
UNNAMED_9_CAP_I180_N2 on BOTTOM: 65.87,35.52 65.61,35.26 65.61,33.23 67.14,33.23 67.14,32.72 68.41,32.72 69.3,33.61 77.78,33.61 77.78,33.64 77.78,40.22 74.5,40.22 74.12,40.6 72.34,40.6 72.34,35.52

Small or netless copper shapes (teardrops, artwork), in the pictures only: 1 on BOTTOM

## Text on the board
Ref Des/Silkscreen Bottom: 038526 REV C
Ref Des/Silkscreen Top: AD-FMCDAQ3-EBZ
ROOT_NUMBER: 038526 | REV C
PAGE_OUTLINE: B | C | AS PER ECR-053374 | AS PER ECR-064781 | 08SEP15 | 28SEP16 | C.EL-KHOURY
DIMENSION: .030 R | 2.598 | 2.496 | 2.413 | .012 | -.118 | 3 PLACES | FAB NOTE 15 | 3.102 | REF. | "0" | 2.717 | -2.378 | -2.130 | -1.705 | -1.516 | .724
User.13: L2 AGND | 08-      -07
User.14: 08-      -08 | L3 SIG
User.15: 08-      -09 | L4 GND
User.16: L5 SIG | 08-      -10
User.17: L6 PWR | 08-      -11
User.18: 08-      -12 | L7 AGND
User.20: CHARACTERISTIC IMPEDANCE = 100 OHMS DIFF +/-10% | ARTWORK LINE WIDTH FOR | IMPEDANCE CONTROLLED LINES = L/S 0.010"/0.010" @ L1, L3, L8 and L10 | ENIG (Electroless Nickel/Immersion Gold) | PER IPC-4552 LATEST REVISION | AD9680 CUSTOMER EVAL BOARD Z
User.21: L8 SIG | 08-      -13
User.22: L9 AGND | 08-      -14
User.29: 3 | 4 | BURIED VIA L2-L9 | DIA MAX
User.30: 4 | BLIND VIA L9-L10 | SEE FAB NOTE 15
User.31: 2 | 4 | BLIND VIA L1-L2 | SEE FAB NOTE 15
User.35: PRIMARY SIDE ASSEMBLY
User.36: SECONDARY SIDE ASSEMBLY
User.45: FIGURE | SIZE | 10.0 | 8.0 | 50.0 | 87.0 | 106.0 | PLATED | NON-PLATED | FINISHED HOLES IN MILS | ALL UNITS ARE IN MILS | QTY | 1099 | 785 | 807 | 847 | 2 | 4 | TOLERANCE/NOTES
